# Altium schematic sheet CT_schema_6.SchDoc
size 302 x 256 mm
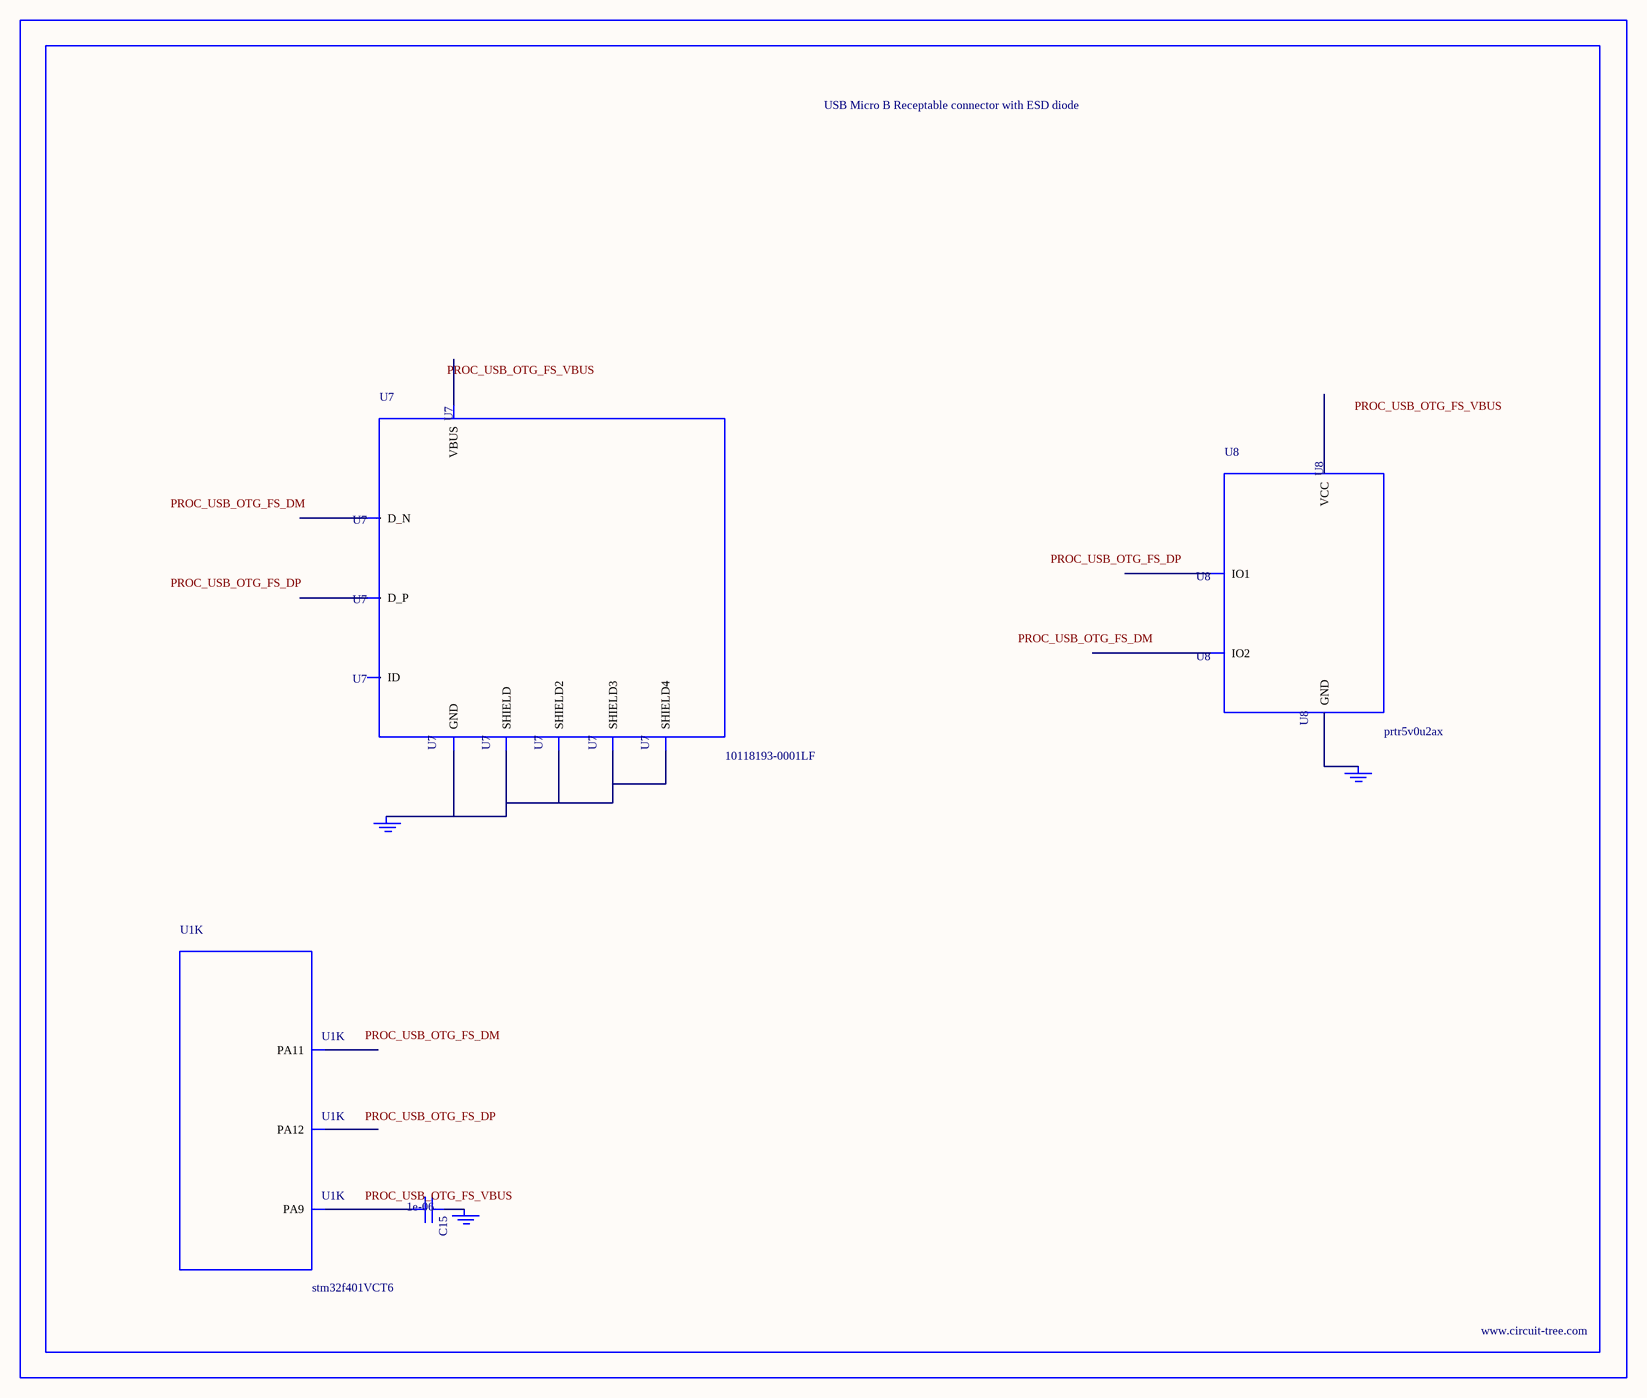
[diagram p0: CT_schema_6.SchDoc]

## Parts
BORDER5  (no value)
C15  1e-06  [C0603]
GND_INSTANCE_5_0  (no value)
GND_INSTANCE_5_1  (no value)
GND_INSTANCE_5_2  (no value)
U1  stm32f401VCT6  [LQFP100]  (part K of 11)
U7  10118193-0001LF  [FCI_10118193-0001LF]
U8  prtr5v0u2ax  [SOT143B]

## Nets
NetC15_1: C15.1 GND_INSTANCE_5_1.0(GND)
NetC15_2: C15.2 U1.68(PA9)
NetGND_INSTANCE_5_0_0: GND_INSTANCE_5_0.0(GND) U7.5(GND) U7.6(SHIELD) U7.7(SHIELD2) U7.8(SHIELD3) U7.9(SHIELD4)
NetGND_INSTANCE_5_2_0: GND_INSTANCE_5_2.0(GND) U8.1(GND)

Not connected (* = marked no-connect by the designer): U1 70(PA11) 71(PA12); U7 1(VBUS) 2(D_N) 3(D_P) 4(ID); U8 2(IO1) 3(IO2) 4(VCC)

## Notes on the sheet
- Labels drawn without touching a wire or pin: PROC_USB_OTG_FS_DM, PROC_USB_OTG_FS_DP, PROC_USB_OTG_FS_VBUS

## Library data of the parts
BORDER5 = BORDER_PAGE5
C15 = C0603C105K3RACTU
GND_INSTANCE_5_0-GND_INSTANCE_5_2 = GND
